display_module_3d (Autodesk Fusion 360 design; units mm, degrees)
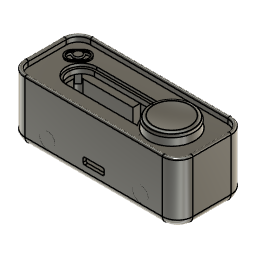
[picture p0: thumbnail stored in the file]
sketch "top&slot" plane through (0, 0, 0) normal (0, 0, 1) x axis (1, 0, 0)
  line L1 (22, -14.5) -> (22, -20.5)
  line L2 (11, 0) -> (-40.5, 0)
  line L3 (-45, 20.35) -> (45, 20.35)
  line L4 (-45, 20.5) -> (45, 20.5)
  line L5 (45, -22.5) -> (-45, -22.5)
  line L6 (-45, 15.5) -> (45, 15.5)
  line L7 (-45, 14.5) -> (45, 14.5)
  line L8 (17.5, 10) -> (17.41, 10)
  line L9 (17.5, 8.5) -> (-30.5, 8.5)
  line L10 (-14.75, 0) -> (11, 0)
  line L11 (-45, 22.5) -> (45, 22.5)
  line L12 (-20, -20.5) -> (-20, -16.5)
  line L13 (15, -14.5) -> (-15, -14.5)
  line L14 (17.5, 10) -> (-30.5, 10)
  line L15 (22, -18.4) -> (3.25, -18.4)
  line L16 (-22, -14.5) -> (-15, -14.5)
  line L17 (-55, -12.5) -> (-55, 12.5)
  line L18 (17.5, -10) -> (17.5, 10)
  line L19 (48, 12.5) -> (48, -12.5)
  line L20 (0, -20.5) -> (0, 20.5)
  line L21 (-47, -12.5) -> (-47, 12.5)
  line L22 (15, -16.5) -> (15, -14.5)
  line L23 (-15, -17.5) -> (-15, -14.5)
  line L24 (20, -16.5) -> (-20, -16.5)
  line L25 (45, -15.5) -> (-45, -15.5)
  line L26 (-8, 0) -> (-53, 0)
  line L27 (-3.25, -16.5) -> (-3.25, -18.4)
  line L28 (20, -20.5) -> (20, -16.5)
  line L29 (-15, -18.4) -> (-15, -17.5)
  line L30 (3.25, -16.5) -> (3.25, -18.4)
  line L31 (45, -20.35) -> (-45, -20.35)
  line L32 (-22, -14.5) -> (-22, -20.5)
  line L33 (-30.5, -8.5) -> (17.5, -8.5)
  line L34 (-3.25, -18.4) -> (3.25, -18.4)
  line L35 (-22, -18.4) -> (-3.25, -18.4)
  line L36 (-30.5, -10) -> (17.5, -10)
  line L37 (0, -19.5) -> (0, -14.5)
  line L38 (22, -19.5) -> (-22, -19.5)
  line L39 (22, -14.5) -> (15, -14.5)
  line L40 (45, -14.5) -> (-45, -14.5)
  line L41 (45, -20.5) -> (-45, -20.5)
  line L42 (20, -20.5) -> (20, -17.5)
  line L43 (53, 12.5) -> (53, -12.5)
  line L44 (-30.5, 10) -> (-30.5, -10)
  line L45 (-55, -22.5) -> (55, 22.5)
  line L46 (17.5, -8.5) -> (17.5, 8.5)
  line L47 (-52.85, -12.5) -> (-52.85, 12.5)
  line L48 (55, -22.5) -> (-55, 22.5)
  line L49 (47, 12.5) -> (47, -12.5)
  line L50 (55, 12.5) -> (55, -12.5)
  line L51 (-30.5, 8.5) -> (-30.5, -8.5)
  line L52 (52.85, 12.5) -> (52.85, -12.5)
  line L53 (-48, -12.5) -> (-48, 12.5)
  line L54 (-53, -12.5) -> (-53, 12.5)
  line L55 (-12.3, 15.5) -> (-45, 15.5)
  line L56 (-12.3, 20.5) -> (-12.3, 15.5)
  line L57 (-45, 20.5) -> (-12.3, 20.5)
  line L58 (-45, 15.5) -> (-45, 20.5)
  line L59 (8.3, 15.5) -> (45, 15.5)
  line L60 (8.3, 20.5) -> (8.3, 15.5)
  line L61 (45, 20.5) -> (8.3, 20.5)
  line L62 (45, 15.5) -> (45, 20.5)
  arc A1 centre (45, 12.5) radius 10 clockwise from (45, 22.5) to (55, 12.5)
  circle C1 centre (-30.5, 0) radius 10
  arc A2 centre (45, 12.5) radius 8 clockwise from (45, 20.5) to (53, 12.5)
  arc A3 centre (45, 12.5) radius 7.85 clockwise from (45, 20.35) to (52.85, 12.5)
  arc A4 centre (-30.5, 0) radius 8.5 clockwise from (-30.5, -8.5) to (-30.5, 8.5)
  arc A5 centre (-45, 12.5) radius 8 clockwise from (-53, 12.5) to (-45, 20.5)
  arc A6 centre (-45, -12.5) radius 10 clockwise from (-45, -22.5) to (-55, -12.5)
  arc A7 centre (45, 12.5) radius 2 clockwise from (45, 14.5) to (47, 12.5)
  arc A8 centre (45, -12.5) radius 7.85 clockwise from (52.85, -12.5) to (45, -20.35)
  arc A9 centre (45, -12.5) radius 10 clockwise from (55, -12.5) to (45, -22.5)
  arc A10 centre (45, -12.5) radius 2 clockwise from (47, -12.5) to (45, -14.5)
  arc A11 centre (45, 12.5) radius 3 clockwise from (45, 15.5) to (48, 12.5)
  arc A12 centre (-45, -12.5) radius 3 clockwise from (-45, -15.5) to (-48, -12.5)
  arc A13 centre (-45, -12.5) radius 7.85 clockwise from (-45, -20.35) to (-52.85, -12.5)
  arc A14 centre (-45, -12.5) radius 2 clockwise from (-45, -14.5) to (-47, -12.5)
  arc A15 centre (45, -12.5) radius 8 clockwise from (53, -12.5) to (45, -20.5)
  arc A16 centre (45, -12.5) radius 3 clockwise from (48, -12.5) to (45, -15.5)
  arc A17 centre (-45, -12.5) radius 8 clockwise from (-45, -20.5) to (-53, -12.5)
  circle C2 centre (28.635, 0.0503) radius 14.9999
  arc A18 centre (-45, 12.5) radius 7.85 clockwise from (-52.85, 12.5) to (-45, 20.35)
  circle C3 centre (28.635, 0.0503) radius 15.9999
  arc A19 centre (-45, 12.5) radius 3 clockwise from (-48, 12.5) to (-45, 15.5)
  arc A20 centre (-45, 12.5) radius 10 clockwise from (-55, 12.5) to (-45, 22.5)
  arc A21 centre (-45, 12.5) radius 2 clockwise from (-47, 12.5) to (-45, 14.5)
  point P89 (0, 0)
  point P94 (0, 0)
  point P92 (-55, 22.5)
  point P93 (-55, -22.5)
  point P90 (55, -22.5)
  point P91 (55, 22.5)
  point P100 (-53, 0)
  point P98 (-8, 0)
  point P99 (-8, 0)
  point P96 (-40.5, 0)
  point P102 (-14.75, 0)
  point P97 (-14.75, 0)
  point P37 (0, 20.5)
  point P86 (0, -14.5)
  point P87 (0, -19.5)
  point P88 (0, -20.5)
  point P51 (-30.5, 10)
  point P66 (17.41, 10)
  point P54 (17.5, -10)
  point P64 (17.5, -8.5)
  point P72 (-30.5, 8.5)
  point P47 (22, -19.5)
  point P5 (22, -20.5)
  point P25 (-22, -19.5)
  point P2 (-22, -20.5)
  point P3 (-20, -20.5)
  point P53 (17.5, 10)
  point P52 (-30.5, -10)
  point P71 (-30.5, -8.5)
  point P105 (-45, 15.5)
  point P119 (-12.3, 15.5)
  point P114 (45, 15.5)
  point P122 (8.3, 15.5)
  point P124 (45, 20.5)
  horizontal L11
  perpendicular L11 L17
  parallel L5 L11
  parallel L17 L50
  coincident P89 L45
  coincident P89 L48
  coincident P89 P94
  coincident P92 L11
  coincident P92 L17
  tangent L11 A20
  tangent L17 A20
  coincident P93 L17
  coincident P93 L5
  tangent L17 A6
  tangent L5 A6
  equal A6 A20
  coincident P90 L50
  coincident P90 L5
  tangent A9 L50
  tangent L5 A9
  equal A9 A20
  coincident P91 L11
  coincident P91 L50
  tangent A1 L11
  tangent A1 L50
  equal A1 A20
  midpoint P100 L54
  perpendicular L26 L54
  coincident P98 P99
  coincident P96 C1
  coincident P96 L26
  midpoint P102 L2
  coincident P97 P102
  midpoint P37 L4
  perpendicular L20 L41
  midpoint P86 L13
  midpoint P87 L38
  coincident P88 L41
  horizontal L14
  vertical L18
  horizontal L36
  vertical L44
  coincident P51 C1
  coincident P66 L14
  coincident P66 C2
  coincident P54 C2
  horizontal L9
  vertical L46
  horizontal L33
  vertical L51
  coincident P64 L18
  coincident P72 L44
  concentric C1 A4
  coincident P47 L1
  coincident P5 L41
  coincident P25 L32
  coincident P2 L41
  coincident P3 L41
  horizontal L55
  vertical L56
  horizontal L57
  vertical L58
  horizontal L59
  vertical L60
  horizontal L61
  vertical L62
  dimension "d1" = -2
  dimension "d2" = -2.15
  dimension "d3" = 1
  dimension "d4" = -8
  dimension "d5" = -7
  dimension "d6" distance P90 P93 = 110
  dimension "d7" distance P92 P93 = 45
  dimension "d8" radius A20 = 10
  dimension "d9" distance P99 P100 = 45
  dimension "d10" distance P51 P53 = 48
  dimension "d11" distance P51 P52 = 20
  dimension "d12" distance P71 P72 = 17
  dimension "d56" distance P105 P119 = 32.7
  dimension "d57" distance P114 P122 = 36.7
  dimension "d58" distance P114 P124 = 5
extrude "Extrude1" new body sketch "top&slot" profile of L1 L9 C1 L12 L13 L14 L15 L16 L22 L23 L24 L27 L28 L29 L30 L32 L33 L34 L35 L36 L38 L39 L42 C2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 along normal blind 5
sketch "switch" plane through (0, 0, 0) normal (0, 0, 1) x axis (1, 0, 0)
  line L1 (-72.5, -10.85) -> (-72.5, -1.85)
  line L2 (-71.5, -6.35) -> (-89.5, -6.35)
  line L3 (-74.5, -2.85) -> (-86.5, -9.85)
  line L4 (-88.5, -10.85) -> (-72.5, -10.85)
  line L5 (-74.5, -2.85) -> (-86.5, -2.85)
  line L6 (-86.5, -2.85) -> (-86.5, -9.85)
  line L7 (-88.5, -1.85) -> (-72.5, -10.85)
  line L8 (-71.5, -1.6) -> (-89.5, -1.6)
  line L9 (-88.5, -1.85) -> (-88.5, -10.85)
  line L10 (-80.5, -11.1) -> (-80.5, -1.6)
  line L11 (-89.5, -1.6) -> (-89.5, -11.1)
  line L12 (-86.5, -2.85) -> (-74.5, -9.85)
  line L13 (-72.5, -1.85) -> (-88.5, -1.85)
  line L14 (-74.5, -9.85) -> (-74.5, -2.85)
  line L15 (-89.5, -11.1) -> (-71.5, -11.1)
  line L16 (-71.5, -11.1) -> (-71.5, -1.6)
  line L17 (-72.5, -1.85) -> (-88.5, -10.85)
  line L18 (-86.5, -9.85) -> (-74.5, -9.85)
  line L19 (-32.6602, 12.746) -> (-39.3777, 19.4635)
  line L20 (-45.3881, 0.0181) -> (-32.6602, 12.746)
  line L21 (-39.3777, 19.4635) -> (-52.1057, 6.7356)
  line L22 (-52.1057, 6.7356) -> (-45.3881, 0.0181)
  line L23 (-33.5441, 12.2157) -> (-39.9081, 18.5796)
  line L24 (-44.8578, 0.902) -> (-33.5441, 12.2157)
  line L25 (-39.9081, 18.5796) -> (-51.2218, 7.2659)
  line L26 (-51.2218, 7.2659) -> (-44.8578, 0.902)
  line L27 (-34.2512, 11.5086) -> (-40.6152, 17.8725)
  line L28 (-44.1507, 1.6091) -> (-34.2512, 11.5086)
  line L29 (-40.6152, 17.8725) -> (-50.5147, 7.973)
  line L30 (-50.5147, 7.973) -> (-44.1507, 1.6091)
  line L31 (-35.6654, 11.5086) -> (-40.6152, 16.4583)
  line L32 (-44.1507, 3.0233) -> (-35.6654, 11.5086)
  line L33 (-40.6152, 16.4583) -> (-49.1005, 7.973)
  line L34 (-49.1005, 7.973) -> (-44.1507, 3.0233)
  line L35 (16.1856, -10) -> (-30.5, -10)
  line L36 (-30.5, 10) -> (16.105, 10)
  line L37 (22, -14.5) -> (22, -14.509)
  line L38 (21.9803, -14.5) -> (22, -14.5)
  line L39 (52.85, -12.5) -> (52.85, 12.5)
  line L40 (-45, -20.35) -> (45, -20.35)
  line L41 (-52.85, 12.5) -> (-52.85, -12.5)
  line L42 (45, 20.35) -> (-45, 20.35)
  line L43 (-52.35, 12.5) -> (-52.35, -12.5)
  line L44 (-45, -19.85) -> (45, -19.85)
  line L45 (52.35, -12.5) -> (52.35, 12.5)
  line L46 (45, 19.85) -> (-45, 19.85)
  circle C1 centre (-80.5, -6.35) radius 3.25
  circle C2 centre (-42.3829, 9.7408) radius 3.25
  arc A1 centre (-30.5, 0) radius 10 clockwise from (-30.5, -10) to (-30.5, 10)
  arc A2 centre (28.635, 0.0503) radius 15.9999 clockwise from (16.1856, -10) to (16.105, 10)
  circle C3 centre (28.635, 0.0503) radius 14.9999
  arc A3 centre (28.635, 0.0503) radius 15.9999 clockwise from (22, -14.509) to (21.9803, -14.5)
  arc A4 centre (45, -12.5) radius 7.85 clockwise from (52.85, -12.5) to (45, -20.35)
  arc A5 centre (-45, -12.5) radius 7.85 clockwise from (-45, -20.35) to (-52.85, -12.5)
  arc A6 centre (-45, 12.5) radius 7.85 clockwise from (-52.85, 12.5) to (-45, 20.35)
  arc A7 centre (45, 12.5) radius 7.85 clockwise from (45, 20.35) to (52.85, 12.5)
  arc A8 centre (-45, 12.5) radius 7.35 clockwise from (-52.35, 12.5) to (-45, 19.85)
  arc A9 centre (-45, -12.5) radius 7.35 clockwise from (-45, -19.85) to (-52.35, -12.5)
  arc A10 centre (45, -12.5) radius 7.35 clockwise from (52.35, -12.5) to (45, -19.85)
  arc A11 centre (45, 12.5) radius 7.35 clockwise from (45, 19.85) to (52.35, 12.5)
  point P13 (-80.5, -1.6)
  point P4 (-80.5, -11.1)
  point P5 (-89.5, -6.35)
  point P6 (-71.5, -6.35)
  point P9 (-80.5, -6.35)
  point P15 (-80.5, -6.35)
  point P23 (-80.5, -6.35)
  point P2 (-89.5, -1.6)
  point P8 (-71.5, -1.6)
  point P3 (-89.5, -11.1)
  point P12 (-86.5, -2.85)
  point P14 (-74.5, -2.85)
  point P11 (-86.5, -9.85)
  point P17 (-88.5, -1.85)
  point P19 (-72.5, -1.85)
  point P18 (-88.5, -10.85)
  point P32 (-52.1057, 6.7356)
  point P37 (-39.3777, 19.4635)
  point P20 (-45.3881, 0.0181)
  point P27 (-40.6152, 16.4583)
  point P30 (-49.1005, 7.973)
  point P24 (-44.1507, 3.0233)
  point P26 (-51.2218, 7.2659)
  point P28 (-39.9081, 18.5796)
  point P31 (-44.8578, 0.902)
  midpoint P13 L8
  midpoint P4 L15
  midpoint P5 L11
  midpoint P6 L16
  midpoint P9 L10
  perpendicular L6 L18
  parallel L5 L18
  parallel L6 L14
  coincident P15 L12
  coincident P15 L3
  coincident P9 P15
  perpendicular L4 L9
  parallel L4 L13
  parallel L1 L9
  coincident P23 L7
  coincident P23 L17
  coincident P9 P23
  perpendicular L32 L34
  parallel L32 L33
  parallel L31 L34
  perpendicular L24 L26
  parallel L24 L25
  parallel L23 L26
  dimension "d15" = -1
  dimension "d16" distance P2 P8 = 18
  dimension "d17" distance P2 P3 = 9.5
  dimension "d18" diameter C1 = 6.5
  dimension "d19" distance P12 P14 = 12
  dimension "d20" distance P11 P12 = 7
  dimension "d21" distance P17 P19 = 16
  dimension "d22" distance P17 P18 = 9
  dimension "d23" distance P32 P37 = 18
  dimension "d24" distance P20 P32 = 9.5
  dimension "d25" diameter C2 = 6.5
  dimension "d26" distance P27 P30 = 12
  dimension "d27" distance P24 P30 = 7
  dimension "d28" distance P26 P28 = 16
  dimension "d29" distance P26 P31 = 9
  dimension "d82" = 0.5
extrude "Extrude2" new body sketch "top&slot" profile of L1 A1 L5 L8 L9 C1 L11 L12 L13 L14 L15 L16 L17 L18 A4 L22 A6 L23 L24 L27 L28 A9 L29 L30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 along normal blind 9.9 (= "7 mm + 2.9 mm") and against normal blind 30
extrude "Extrude3" add sketch "top&slot" profile of L9 C1 L14 A4 L33 L36 L44 C3 along normal blind 3.1
shell "Shell1" innerThickness 2
fillet "Fillet1" radius 5
extrude "Extrude4" sketch "top&slot" profile of L1 L12 L15 L22 L23 L24 L28 L32 L34 L35 L38 L42 L4 L54 L41 L43 A5 A17 A15 A2 L3 L47 L31 L52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 blind 17.2 (= "19.2 mm - 2 mm")
sketch "magnet" plane through (0, -15.5, 0) normal (0, 1, 0) x axis (-1, 0, 0)
  line L1 (-15, -28) -> (-45, -28)
  line L2 (-15, -10.8) -> (-15, -28)
  line L3 (-45, -10.8) -> (-15, -10.8)
  line L4 (-45, -28) -> (-45, -10.8)
  line L5 (45, -28) -> (15, -28)
  line L6 (45, -10.8) -> (45, -28)
  line L7 (15, -10.8) -> (45, -10.8)
  line L8 (15, -28) -> (15, -10.8)
  line L9 (-30.5, -19.4) -> (-15, -19.4)
  line L10 (-15, -19.4) -> (15, -19.4)
  line L11 (0, -32) -> (0, -19.4)
  circle C1 centre (-30.5, -19.4) radius 5.1
  circle C2 centre (30.5, -19.4) radius 5.1
  point P10 (-15, -19.4)
  point P11 (-30.5, -19.4)
  point P12 (-30.5, -19.4)
  point P13 (15, -19.4)
  point P14 (0, -19.4)
  midpoint L2 P10
  perpendicular L2 L9
  coincident P11 P12
  midpoint L8 P13
  midpoint L10 P14
  perpendicular L10 L11
  symmetric C1 L11 C2
  dimension "d42" distance P10 P11 = 15.5
  dimension "d43" diameter C1 = 10.2
extrude "Extrude5" cut sketch "magnet" profile of C1 C2 against normal blind 6.5
sketch "usb" plane through (0, 22.5, 0) normal (0, 1, 0) x axis (-1, 0, 0)
  line L1 (45, -25) -> (-45, -25)
  line L2 (45, 9.9) -> (45, -25)
  line L3 (-45, 9.9) -> (45, 9.9)
  line L4 (-45, -25) -> (-45, 9.9)
  line L5 (-3.5, -20.78) -> (5.5, -20.78)
  line L6 (-3.5, -17.58) -> (-3.5, -20.78)
  line L7 (5.5, -17.58) -> (-3.5, -17.58)
  line L8 (5.5, -20.78) -> (5.5, -17.58)
  line L9 (5.7, -17.38) -> (-3.7, -17.38)
  line L10 (5.7, -20.98) -> (5.7, -17.38)
  line L11 (-3.7, -20.98) -> (5.7, -20.98)
  line L12 (-3.7, -17.38) -> (-3.7, -20.98)
  point P6 (5.5, -20.78)
  point P7 (-3.5, -20.78)
  point P9 (5.5, -17.58)
  horizontal L5
  vertical L6
  horizontal L7
  vertical L8
  dimension "d49" distance P6 P7 = 9
  dimension "d50" distance P6 P9 = 3.2
  dimension "d51" = -0.2
extrude "Extrude6" cut sketch "usb" profile of L5 L6 L7 L8 L10 L11 L9 L12 against normal blind 8
fillet "Fillet2" radius 1.5
extrude "Extrude7" cut sketch "top&slot" profile of L4 L3 L6 L56 L60 to an object
sketch "pogo" plane through (0, -18.4, 0) normal (0, 1, 0) x axis (-1, 0, 0)
  line L1 (20, -28) -> (-20, -28)
  line L2 (20, -10.8) -> (20, -28)
  line L3 (-20, -10.8) -> (20, -10.8)
  line L4 (-20, -28) -> (-20, -10.8)
  line L5 (10, -24) -> (-10, -24)
  line L6 (20, -28) -> (-20, -28)
  line L7 (-20, -16.4) -> (-1.7101, -16.4)
  line L8 (-6.92, -17.81) -> (-6.92, -20.19)
  line L9 (5.92, -16.81) -> (-5.92, -16.81)
  line L10 (-1.7101, -16.4) -> (0, -16.4)
  line L11 (20, -16.4) -> (0, -16.4)
  line L12 (20, -4.8) -> (20, -28)
  line L13 (20, -28) -> (-20, -28)
  line L14 (20, -11.8) -> (20, -28)
  line L15 (-20, -11.8) -> (20, -11.8)
  line L16 (6.92, -20.19) -> (6.92, -17.81)
  line L17 (-20, -4.8) -> (20, -4.8)
  line L18 (0, -28) -> (0, -4.8)
  line L19 (0, -24) -> (0, -14)
  line L20 (-20, -28) -> (-20, -4.8)
  line L21 (-10, -14) -> (10, -14)
  line L22 (-5.92, -21.19) -> (5.92, -21.19)
  line L23 (-20, -28) -> (-20, -11.8)
  line L24 (24, -28) -> (0, -28)
  arc A1 centre (-10, -19) radius 5 clockwise from (-10, -24) to (-15, -19)
  arc A2 centre (-5.92, -17.81) radius 1 clockwise from (-6.92, -17.81) to (-5.92, -16.81)
  arc A3 centre (10, -19) radius 5 clockwise from (15, -19) to (10, -24)
  arc A4 centre (5.92, -20.19) radius 1 clockwise from (6.92, -20.19) to (5.92, -21.19)
  arc A5 centre (5.92, -17.81) radius 1 clockwise from (5.92, -16.81) to (6.92, -17.81)
  arc A6 centre (10, -19) radius 5 clockwise from (10, -14) to (15, -19)
  arc A7 centre (-5.92, -20.19) radius 1 clockwise from (-5.92, -21.19) to (-6.92, -20.19)
  arc A8 centre (-10, -19) radius 5 clockwise from (-15, -19) to (-10, -14)
  point P13 (0, -4.8)
  point P29 (0, -28)
  point P44 (0, -16.4)
  point P12 (-20, -16.4)
  point P37 (20, -16.4)
  point P42 (15, -19)
  point P43 (15, -19)
  point P6 (-15, -19)
  point P40 (-15, -19)
  point P22 (0, -14)
  point P24 (0, -24)
  midpoint P13 L17
  midpoint P29 L6
  midpoint P44 L18
  perpendicular L10 L18
  midpoint P12 L20
  perpendicular L7 L20
  midpoint P37 L12
  perpendicular L18 L24
  horizontal L5
  horizontal L21
  tangent A6 L21
  tangent L5 A3
  equal A3 A6
  coincident P42 P43
  tangent L21 A8
  equal A6 A8
  tangent L5 A1
  equal A1 A6
  coincident P6 P40
  horizontal L22
  perpendicular L8 L22
  parallel L9 L22
  parallel L8 L16
  tangent A2 L8
  tangent A2 L9
  tangent L8 A7
  tangent A7 L22
  equal A2 A7
  tangent A4 L22
  tangent A4 L16
  equal A2 A4
  tangent L9 A5
  tangent A5 L16
  midpoint P22 L21
  midpoint P24 L5
  dimension "d61" radius A6 = 5
  dimension "d62" distance L5 L21 = 10
  dimension "d63" radius A2 = 1
  dimension "d64" radius A5 = 1
extrude "Extrude8" cut sketch "pogo" profile of L5 A1 A2 L8 A3 L9 A4 A5 A6 L16 A7 L19 L21 L22 A8 against normal blind 2.1
sketch "slider" plane through (0, 0, 0) normal (0, 0, -1) x axis (1, 0, 0)
  line L1 (-30.5, -8.5) -> (15.0483, -8.5)
  line L2 (15.1114, 8.5) -> (-30.5, 8.5)
  line L3 (22, 14.5) -> (22, 14.509)
  line L4 (21.9803, 14.5) -> (22, 14.5)
  line L5 (52.85, 12.5) -> (52.85, -12.5)
  line L6 (-45, 20.35) -> (45, 20.35)
  line L7 (-52.85, -12.5) -> (-52.85, 12.5)
  line L8 (45, -20.35) -> (-45, -20.35)
  line L9 (-50.5725, -7.9652) -> (-40.673, -17.8647)
  line L10 (-40.673, -17.8647) -> (-34.3091, -11.5007)
  line L11 (-42.4408, -20.35) -> (-42.4408, -9.7329)
  line L12 (-33.602, -12.2078) -> (-44.9157, -0.8941)
  line L13 (-45, -9.7329) -> (-45, -20.35)
  line L14 (-34.3091, -11.5007) -> (-44.2086, -1.6012)
  line L15 (-51.2796, -7.2581) -> (-39.9659, -18.5718)
  line L16 (-44.2086, -3.0154) -> (-49.1583, -7.9652)
  line L17 (-44.2086, -1.6012) -> (-50.5725, -7.9652)
  line L18 (-45.446, -0.0102) -> (-52.1635, -6.7277)
  line L19 (-52.4408, -12.5) -> (-52.85, -12.5)
  line L20 (-35.7233, -11.5007) -> (-44.2086, -3.0154)
  line L21 (-49.1583, -7.9652) -> (-40.673, -16.4505)
  line L22 (-39.4356, -19.4557) -> (-32.7181, -12.7382)
  line L23 (-39.9659, -18.5718) -> (-33.602, -12.2078)
  line L24 (-52.1635, -6.7277) -> (-39.4356, -19.4557)
  line L25 (-42.4408, -12.5) -> (-52.4408, -12.5)
  line L26 (-52.85, -9.7329) -> (-42.4408, -9.7329)
  line L27 (-32.7181, -12.7382) -> (-45.446, -0.0102)
  line L28 (-44.9157, -0.8941) -> (-51.2796, -7.2581)
  line L29 (-40.673, -16.4505) -> (-35.7233, -11.5007)
  arc A1 centre (28.635, -0.0503) radius 15.9999 clockwise from (15.0483, -8.5) to (15.1114, 8.5)
  arc A2 centre (-30.5, 0) radius 8.5 clockwise from (-30.5, -8.5) to (-30.5, 8.5)
  circle C1 centre (28.635, -0.0503) radius 14.9999
  arc A3 centre (28.635, -0.0503) radius 15.9999 clockwise from (21.9803, 14.5) to (22, 14.509)
  arc A4 centre (45, 12.5) radius 7.85 clockwise from (45, 20.35) to (52.85, 12.5)
  arc A5 centre (-45, 12.5) radius 7.85 clockwise from (-52.85, 12.5) to (-45, 20.35)
  arc A6 centre (-45, -12.5) radius 7.85 clockwise from (-45, -20.35) to (-52.85, -12.5)
  arc A7 centre (45, -12.5) radius 7.85 clockwise from (52.85, -12.5) to (45, -20.35)
  circle C2 centre (-42.4408, -9.7329) radius 3.25
  point P36 (-42.4408, -9.7329)
  point P48 (-42.4408, -9.7329)
  point P24 (-52.85, -12.5)
  point P49 (-52.85, -12.5)
  point P51 (-42.4408, -12.5)
  point P23 (-45, -20.35)
  point P45 (-45, -20.35)
  point P46 (-45, -9.7329)
  point P39 (-39.4356, -19.4557)
  point P44 (-52.1635, -6.7277)
  point P28 (-32.7181, -12.7382)
  point P34 (-49.1583, -7.9652)
  point P37 (-40.673, -16.4505)
  point P31 (-35.7233, -11.5007)
  point P33 (-39.9659, -18.5718)
  point P35 (-51.2796, -7.2581)
  point P38 (-33.602, -12.2078)
  perpendicular L20 L29
  parallel L20 L21
  parallel L16 L29
  perpendicular L12 L23
  parallel L12 L15
  parallel L23 L28
  coincident P36 P48
  coincident P24 P49
  coincident P51 L11
  perpendicular L11 L25
  coincident P23 P45
  coincident P46 L26
  perpendicular L13 L26
  dimension "d84" distance P39 P44 = 18
  dimension "d85" distance P28 P39 = 9.5
  dimension "d86" diameter C2 = 6.5
  dimension "d87" distance P34 P37 = 12
  dimension "d88" distance P31 P37 = 7
  dimension "d89" distance P33 P35 = 16
  dimension "d90" distance P33 P38 = 9
extrude "Extrude15" cut sketch "slider" profile of L16 L20 L21 C2 L29 along normal blind 9
extrude "Extrude17" sketch "slider" profile of L12 L15 L16 L18 L20 L21 L22 L23 L24 L27 L28 L29 L17 L14 L9 L10 blind -3.5
extrude "Extrude18" sketch "slider" profile of L12 L15 L16 L20 L21 L23 L28 C2 L29 L17 L14 L9 L10 blind 1 bodies "switch"
fillet "Fillet3" radius 4.4
fillet "Fillet4" radius 4.5
sketch "sliderclose" plane through (0, 0, 0) normal (0, 0, -1) x axis (1, 0, 0)
  line L1 (-48.628, -3.1922) -> (-48.9815, -3.5458)
  line L2 (-35.9001, -9.5562) -> (-42.264, -3.1922)
  line L3 (-36.2536, -16.2737) -> (-35.9001, -15.9201)
  line L4 (-48.9815, -9.9097) -> (-42.6176, -16.2737)
  line L5 (-30.5, -8.5) -> (15.0483, -8.5)
  line L6 (15.1114, 8.5) -> (-30.5, 8.5)
  line L7 (22, 14.5) -> (22, 14.509)
  line L8 (21.9803, 14.5) -> (22, 14.5)
  line L9 (52.85, 12.5) -> (52.85, -12.5)
  line L10 (-45, 20.35) -> (45, 20.35)
  line L11 (-52.85, -12.5) -> (-52.85, 12.5)
  line L12 (45, -20.35) -> (-45, -20.35)
  line L13 (-42.6176, -16.2737) -> (-48.9815, -9.9097)
  line L14 (-35.9001, -15.9201) -> (-36.2536, -16.2737)
  line L15 (-42.264, -3.1922) -> (-35.9001, -9.5562)
  line L16 (-48.9815, -3.5458) -> (-48.628, -3.1922)
  line L17 (-43.3247, -16.9808) -> (-49.6887, -10.6168)
  line L18 (-35.193, -16.6272) -> (-35.5465, -16.9808)
  line L19 (-41.5569, -2.4851) -> (-35.193, -8.8491)
  line L20 (-49.6887, -2.8387) -> (-49.3351, -2.4851)
  line L21 (-49.6179, -2.9094) -> (-49.2644, -2.5558)
  line L22 (-43.254, -16.9101) -> (-49.6179, -10.5461)
  line L23 (-35.2637, -16.5565) -> (-35.6172, -16.9101)
  line L24 (-41.6276, -2.5558) -> (-35.2637, -8.9198)
  arc A1 centre (-45.446, -6.3742) radius 4.5 clockwise from (-48.628, -3.1922) to (-42.264, -3.1922)
  arc A2 centre (-39.0821, -12.7382) radius 4.5 clockwise from (-35.9001, -9.5562) to (-35.9001, -15.9201)
  arc A3 centre (-39.4356, -13.0917) radius 4.5 clockwise from (-36.2536, -16.2737) to (-42.6176, -16.2737)
  arc A4 centre (-45.7996, -6.7277) radius 4.5 clockwise from (-48.9815, -9.9097) to (-48.9815, -3.5458)
  arc A5 centre (28.635, -0.0503) radius 15.9999 clockwise from (15.0483, -8.5) to (15.1114, 8.5)
  arc A6 centre (-30.5, 0) radius 8.5 clockwise from (-30.5, -8.5) to (-30.5, 8.5)
  circle C1 centre (28.635, -0.0503) radius 14.9999
  arc A7 centre (28.635, -0.0503) radius 15.9999 clockwise from (21.9803, 14.5) to (22, 14.509)
  arc A8 centre (45, 12.5) radius 7.85 clockwise from (45, 20.35) to (52.85, 12.5)
  arc A9 centre (-45, 12.5) radius 7.85 clockwise from (-52.85, 12.5) to (-45, 20.35)
  arc A10 centre (-45, -12.5) radius 7.85 clockwise from (-45, -20.35) to (-52.85, -12.5)
  arc A11 centre (45, -12.5) radius 7.85 clockwise from (52.85, -12.5) to (45, -20.35)
  arc A12 centre (-45.7996, -6.7277) radius 4.5 clockwise from (-48.9815, -9.9097) to (-48.9815, -3.5458)
  arc A13 centre (-39.4356, -13.0917) radius 4.5 clockwise from (-36.2536, -16.2737) to (-42.6176, -16.2737)
  arc A14 centre (-39.0821, -12.7382) radius 4.5 clockwise from (-35.9001, -9.5562) to (-35.9001, -15.9201)
  arc A15 centre (-45.446, -6.3742) radius 4.5 clockwise from (-48.628, -3.1922) to (-42.264, -3.1922)
  arc A16 centre (-45.7996, -6.7277) radius 5.5 clockwise from (-49.6887, -10.6168) to (-49.6887, -2.8387)
  arc A17 centre (-39.4356, -13.0917) radius 5.5 clockwise from (-35.5465, -16.9808) to (-43.3247, -16.9808)
  arc A18 centre (-39.0821, -12.7382) radius 5.5 clockwise from (-35.193, -8.8491) to (-35.193, -16.6272)
  arc A19 centre (-45.446, -6.3742) radius 5.5 clockwise from (-49.3351, -2.4851) to (-41.5569, -2.4851)
  arc A20 centre (-45.7996, -6.7277) radius 5.4 clockwise from (-49.6179, -10.5461) to (-49.6179, -2.9094)
  arc A21 centre (-39.4356, -13.0917) radius 5.4 clockwise from (-35.6172, -16.9101) to (-43.254, -16.9101)
  arc A22 centre (-39.0821, -12.7382) radius 5.4 clockwise from (-35.2637, -8.9198) to (-35.2637, -16.5565)
  arc A23 centre (-45.446, -6.3742) radius 5.4 clockwise from (-49.2644, -2.5558) to (-41.6276, -2.5558)
  dimension "d105" = 1
  dimension "d108" = 0.9
extrude "Extrude19" cut sketch "sliderclose" profile of L1 A1 L2 A2 L3 A3 L4 A4 A12 L13 A13 L14 A14 L15 A15 L16 L19 L17 A17 L20 A18 A16 A19 L18 against normal blind 2.2
extrude "Extrude20" sketch "slider" profile of C2 blind -4
fillet "Fillet5" radius 3.4
extrude "Extrude21" add sketch "slider" profile of L12 L15 L16 L20 L21 L29 L17 L14 L9 L10 against normal blind 1
fillet "Fillet6" radius 3.4
fillet "Fillet7" radius 3.4
fillet "Fillet8" radius 4.4
sketch "bottommount" plane through (0, 0, -28) normal (0, 0, 1) x axis (-1, 0, 0)
  line L1 (-45, 15.5) -> (-15, 15.5)
  line L2 (-48, -12.5) -> (-48, 12.5)
  line L3 (-8.3, -15.5) -> (-45, -15.5)
  line L4 (-8.3, -20.5) -> (-8.3, -15.5)
  line L5 (12.3, -20.5) -> (-8.3, -20.5)
  line L6 (12.3, -15.5) -> (12.3, -20.5)
  line L7 (45, -15.5) -> (12.3, -15.5)
  line L8 (48, 12.5) -> (48, -12.5)
  line L9 (15, 15.5) -> (45, 15.5)
  line L10 (15, 16.5) -> (15, 15.5)
  line L11 (20, 16.5) -> (15, 16.5)
  line L12 (20, 18.4) -> (20, 16.5)
  line L13 (-20, 18.4) -> (20, 18.4)
  line L14 (-20, 16.5) -> (-20, 18.4)
  line L15 (-15, 16.5) -> (-20, 16.5)
  line L16 (-15, 15.5) -> (-15, 16.5)
  line L17 (-45, 22.5) -> (45, 22.5)
  line L18 (55, 12.5) -> (55, -12.5)
  line L19 (45, -22.5) -> (-45, -22.5)
  line L20 (-55, -12.5) -> (-55, 12.5)
  line L21 (-55, -12.5) -> (-55, 12.5)
  line L22 (45, -22.5) -> (-45, -22.5)
  line L23 (-45, 22.5) -> (45, 22.5)
  line L24 (55, 12.5) -> (55, -12.5)
  arc A1 centre (-45, 12.5) radius 3 clockwise from (-48, 12.5) to (-45, 15.5)
  arc A2 centre (-45, -12.5) radius 3 clockwise from (-45, -15.5) to (-48, -12.5)
  arc A3 centre (45, -12.5) radius 3 clockwise from (48, -12.5) to (45, -15.5)
  arc A4 centre (45, 12.5) radius 3 clockwise from (45, 15.5) to (48, 12.5)
  arc A5 centre (45, 12.5) radius 10 clockwise from (45, 22.5) to (55, 12.5)
  arc A6 centre (-45, -12.5) radius 10 clockwise from (-45, -22.5) to (-55, -12.5)
  arc A7 centre (-45, -12.5) radius 10 clockwise from (-45, -22.5) to (-55, -12.5)
  arc A8 centre (45, 12.5) radius 10 clockwise from (45, 22.5) to (55, 12.5)
  circle C1 centre (43.3243, 10.3844) radius 4
  circle C2 centre (43.3243, 10.3844) radius 2.825
  circle C3 centre (-43.8087, -11.3516) radius 2.825
  circle C4 centre (-43.8087, -11.3516) radius 4
  circle C5 centre (43.3243, 10.3844) radius 1.4
  circle C6 centre (-43.8087, -11.3516) radius 1.55
  dimension "d128" diameter C1 = 8
  dimension "d129" diameter C2 = 5.65
  dimension "d130" diameter C5 = 2.8
  dimension "d131" diameter C6 = 3.1
  dimension "d132" diameter C3 = 5.65
  dimension "d133" diameter C4 = 8
extrude "Extrude22" cut sketch "bottommount" profile of A4 L9 C1 C2 C3 C4 C5 C6 against normal blind 20
extrude "Extrude23" new body sketch "bottommount" profile of A4 L9 C1 C2 C3 C4 along normal blind 9
extrude "Extrude24" cut of existing geometry blind -15
extrude "Extrude25" add sketch "bottommount" profile of C2 C3 C5 C6 blind 5 from offset 2
sketch "Sketch11" plane through (0, 0, 0) normal (0, 0, -1) x axis (1, 0, 0)
  line L1 (-49.3351, -2.4851) -> (-49.6887, -2.8387)
  line L2 (-35.193, -8.8491) -> (-41.5569, -2.4851)
  line L3 (-35.5465, -16.9808) -> (-35.193, -16.6272)
  line L4 (-49.6887, -10.6168) -> (-43.3247, -16.9808)
  line L5 (-30.5, -8.5) -> (15.0483, -8.5)
  line L6 (15.1114, 8.5) -> (-30.5, 8.5)
  line L7 (22, 14.5) -> (22, 14.509)
  line L8 (21.9803, 14.5) -> (22, 14.5)
  line L9 (52.85, 12.5) -> (52.85, -12.5)
  line L10 (-45, 20.35) -> (45, 20.35)
  line L11 (-52.85, -12.5) -> (-52.85, 12.5)
  line L12 (45, -20.35) -> (-45, -20.35)
  arc A1 centre (-45.7996, -6.7277) radius 5.5 clockwise from (-49.6887, -10.6168) to (-49.6887, -2.8387)
  arc A2 centre (-45.446, -6.3742) radius 5.5 clockwise from (-49.3351, -2.4851) to (-41.5569, -2.4851)
  arc A3 centre (-39.0821, -12.7382) radius 5.5 clockwise from (-35.193, -8.8491) to (-35.193, -16.6272)
  arc A4 centre (-39.4356, -13.0917) radius 5.5 clockwise from (-35.5465, -16.9808) to (-43.3247, -16.9808)
  arc A5 centre (28.635, -0.0503) radius 15.9999 clockwise from (15.0483, -8.5) to (15.1114, 8.5)
  arc A6 centre (-30.5, 0) radius 8.5 clockwise from (-30.5, -8.5) to (-30.5, 8.5)
  circle C1 centre (28.635, -0.0503) radius 14.9999
  arc A7 centre (28.635, -0.0503) radius 15.9999 clockwise from (21.9803, 14.5) to (22, 14.509)
  arc A8 centre (45, 12.5) radius 7.85 clockwise from (45, 20.35) to (52.85, 12.5)
  arc A9 centre (-45, 12.5) radius 7.85 clockwise from (-52.85, 12.5) to (-45, 20.35)
  arc A10 centre (-45, -12.5) radius 7.85 clockwise from (-45, -20.35) to (-52.85, -12.5)
  arc A11 centre (45, -12.5) radius 7.85 clockwise from (52.85, -12.5) to (45, -20.35)
  circle C2 centre (-43.3243, 10.3844) radius 4
  circle C3 centre (-43.3243, 10.3844) radius 2.825
  circle C4 centre (-43.3243, 10.3844) radius 1.4
  circle C5 centre (43.8087, -11.3516) radius 4
  circle C6 centre (43.8087, -11.3516) radius 2.825
  circle C7 centre (43.8087, -11.3516) radius 1.55
  circle C8 centre (-43.3243, 10.3844) radius 2.725
  circle C9 centre (43.8087, -11.3516) radius 2.725
  dimension "d143" = -0.1
  dimension "d144" = -0.1
extrude "Extrude26" add sketch "Sketch11" profile of C4 C7 C8 C9 to an object
fillet "Fillet9" radius 0.5
fillet "Fillet10" radius 0.5
sketch "Sketch12" plane through (0, 0, 2.5) normal (0, 0, -1) x axis (1, 0, 0)
  line L1 (-41.8044, -4.0054) -> (-36.7132, -9.0966)
  line L2 (-48.1684, -4.1468) -> (-48.027, -4.0054)
  line L3 (-43.0772, -15.4605) -> (-48.1684, -10.3693)
  line L4 (-36.7132, -15.3191) -> (-36.8547, -15.4605)
  line L5 (-48.0977, -4.0761) -> (-36.784, -15.3898)
  line L6 (-39.2588, -6.551) -> (-45.6228, -12.9149)
  line L7 (-47.5673, -3.5458) -> (-36.2536, -14.8595)
  line L8 (-48.628, -4.6064) -> (-37.3143, -15.9201)
  line L9 (-38.7285, -7.0813) -> (-45.0925, -13.4453)
  line L10 (-39.7892, -6.0206) -> (-46.1531, -12.3846)
  line L11 (-43.5015, -9.7329) -> (-42.4408, -10.7936)
  line L12 (-40.673, -6.9045) -> (-43.5015, -9.7329)
  line L13 (-39.6124, -7.9652) -> (-40.673, -6.9045)
  line L14 (-42.4408, -10.7936) -> (-39.6124, -7.9652)
  line L15 (-40.673, -5.4903) -> (-44.9157, -9.7329)
  line L16 (-38.1982, -7.9652) -> (-40.673, -5.4903)
  line L17 (-42.4408, -12.2078) -> (-38.1982, -7.9652)
  line L18 (-44.9157, -9.7329) -> (-42.4408, -12.2078)
  line L19 (-46.8602, -2.8387) -> (-35.5465, -14.1524)
  line L20 (-49.3351, -5.3135) -> (-38.0214, -16.6272)
  arc A1 centre (-39.8245, -12.2078) radius 4.4 clockwise from (-36.7132, -9.0966) to (-36.7132, -15.3191)
  arc A2 centre (-44.9157, -7.1167) radius 4.4 clockwise from (-48.027, -4.0054) to (-41.8044, -4.0054)
  arc A3 centre (-45.0571, -7.2581) radius 4.4 clockwise from (-48.1684, -10.3693) to (-48.1684, -4.1468)
  arc A4 centre (-39.9659, -12.3492) radius 4.4 clockwise from (-36.8547, -15.4605) to (-43.0772, -15.4605)
  point P14 (-36.784, -15.3898)
  point P15 (-48.0977, -4.0761)
  point P16 (-45.6228, -12.9149)
  point P17 (-39.2588, -6.551)
  point P27 (-43.5015, -9.7329)
  point P26 (-42.4408, -10.7936)
  midpoint L4 P14
  midpoint L2 P15
  midpoint L3 P16
  midpoint L1 P17
  perpendicular L11 L12
  parallel L11 L13
  parallel L12 L14
  coincident L10 P27
  coincident L8 P27
  perpendicular L10 L11
  coincident L9 P26
  dimension "d151" = 0.75 (= "( 1.5 / 2 ) * 1 mm")
  dimension "d152" = -0.75
  dimension "d153" = 0.75 (= "( 1.5 / 2 ) * 1 mm")
  dimension "d154" = -0.75
  dimension "d155" = -1
  dimension "d162" = 1.75 (= "0.75 mm + 1 mm")
  dimension "d163" = -1.75
extrude "Extrude27" add sketch "Sketch12" profile of L11 L12 L13 L14 L15 L16 L18 L17 along normal blind 9
fillet "Fillet11" radius 0.75
extrude "Extrude28" new body sketch "sliderclose" profile of L1 A1 L2 A2 L3 A3 L4 A4 A12 L13 A13 L14 A14 L15 A15 L16 A22 L21 A20 A21 L22 A23 L23 L24 against normal blind 1 bodies "close"
extrude "Extrude29" cut sketch "Sketch12" profile of A1 A2 L2 A3 A4 L4 L11 L12 L13 L14 L15 L16 L18 L17 L19 L20 along normal blind 8
fillet "Fillet12" radius 1
extrude "Extrude30" add of existing geometry blind 2
chamfer "Chamfer1" distance 1
sketch "Sketch13" plane through (0, 0, -30) normal (0, 0, -1) x axis (1, 0, 0)
  line L1 (45, -17.5) -> (-45, -17.5)
  line L2 (50, 12.5) -> (50, -12.5)
  line L3 (-45, 17.5) -> (45, 17.5)
  line L4 (-50, -12.5) -> (-50, 12.5)
  circle C1 centre (43.8087, -11.3516) radius 2.825
  circle C2 centre (-43.3243, 10.3844) radius 4
  arc A1 centre (-45, -12.5) radius 5 clockwise from (-45, -17.5) to (-50, -12.5)
  arc A2 centre (45, -12.5) radius 5 clockwise from (50, -12.5) to (45, -17.5)
  arc A3 centre (45, 12.5) radius 5 clockwise from (45, 17.5) to (50, 12.5)
  arc A4 centre (-45, 12.5) radius 5 clockwise from (-50, 12.5) to (-45, 17.5)
  circle C3 centre (43.8087, -11.3516) radius 4
  concentric C1 C3
  dimension "d171" diameter C3 = 8
extrude "Extrude31" cut sketch "Sketch13" profile of C1 C3 against normal blind 2
extrude "Extrude32" add of existing geometry blind 2
chamfer "Chamfer2" distance 1
sketch "Sketch14" plane through (0, 0, -30) normal (0, 0, -1) x axis (1, 0, 0)
  line L1 (45, -17.5) -> (-45, -17.5)
  line L2 (50, 12.5) -> (50, -12.5)
  line L3 (-45, 17.5) -> (45, 17.5)
  line L4 (-50, -12.5) -> (-50, 12.5)
  circle C1 centre (-43.3243, 10.3844) radius 2.825
  circle C2 centre (43.8087, -11.3516) radius 4
  arc A1 centre (-45, -12.5) radius 5 clockwise from (-45, -17.5) to (-50, -12.5)
  arc A2 centre (45, -12.5) radius 5 clockwise from (50, -12.5) to (45, -17.5)
  arc A3 centre (45, 12.5) radius 5 clockwise from (45, 17.5) to (50, 12.5)
  arc A4 centre (-45, 12.5) radius 5 clockwise from (-50, 12.5) to (-45, 17.5)
  circle C3 centre (-43.3243, 10.3844) radius 4
  concentric C1 C3
  dimension "d179" diameter C3 = 8
extrude "Extrude34" cut sketch "Sketch14" profile of C1 C3 against normal blind 2
sketch "knob" plane through (0, 0, 0) normal (0, 0, -1) x axis (1, 0, 0)
  line L1 (26.835, -2.8162) -> (26.835, 2.7156)
  line L2 (25.335, -3.536) -> (25.335, 3.4354)
  line L3 (27.035, -2.7055) -> (27.035, 2.6049)
  circle C1 centre (28.635, -0.0503) radius 14.9999
  arc A1 centre (28.635, -0.0503) radius 3.3 clockwise from (26.835, 2.7156) to (26.835, -2.8162)
  circle C2 centre (28.635, -0.0503) radius 14.6
  arc A2 centre (28.635, -0.0503) radius 4.8 clockwise from (25.335, 3.4354) to (25.335, -3.536)
  arc A3 centre (28.635, -0.0503) radius 3.1 clockwise from (27.035, 2.6049) to (27.035, -2.7055)
  dimension "d184" diameter C2 = 29.2
  dimension "d188" = 1.5
  dimension "d226" = -0.2
sketch "Sketch18" plane through (0, 0, 0) normal (0, 0, -1) x axis (1, 0, 0)
  line L1 (-49.3351, -2.4851) -> (-49.6887, -2.8387)
  line L2 (-35.193, -8.8491) -> (-41.5569, -2.4851)
  line L3 (-35.5465, -16.9808) -> (-35.193, -16.6272)
  line L4 (-49.6887, -10.6168) -> (-43.3247, -16.9808)
  line L5 (-30.5, -8.5) -> (15.0483, -8.5)
  line L6 (15.1114, 8.5) -> (-30.5, 8.5)
  line L7 (22, 14.5) -> (22, 14.509)
  line L8 (21.9803, 14.5) -> (22, 14.5)
  line L9 (52.85, 12.5) -> (52.85, -12.5)
  line L10 (-45, 20.35) -> (45, 20.35)
  line L11 (-52.85, -12.5) -> (-52.85, 12.5)
  line L12 (45, -20.35) -> (-45, -20.35)
  circle C1 centre (-43.3243, 10.3844) radius 3.225
  arc A1 centre (-45.7996, -6.7277) radius 5.5 clockwise from (-49.6887, -10.6168) to (-49.6887, -2.8387)
  arc A2 centre (-45.446, -6.3742) radius 5.5 clockwise from (-49.3351, -2.4851) to (-41.5569, -2.4851)
  arc A3 centre (-39.0821, -12.7382) radius 5.5 clockwise from (-35.193, -8.8491) to (-35.193, -16.6272)
  arc A4 centre (-39.4356, -13.0917) radius 5.5 clockwise from (-35.5465, -16.9808) to (-43.3247, -16.9808)
  arc A5 centre (28.635, -0.0503) radius 15.9999 clockwise from (15.0483, -8.5) to (15.1114, 8.5)
  arc A6 centre (-30.5, 0) radius 8.5 clockwise from (-30.5, -8.5) to (-30.5, 8.5)
  arc A7 centre (28.635, -0.0503) radius 15.9999 clockwise from (21.9803, 14.5) to (22, 14.509)
  arc A8 centre (45, 12.5) radius 7.85 clockwise from (45, 20.35) to (52.85, 12.5)
  arc A9 centre (-45, 12.5) radius 7.85 clockwise from (-52.85, 12.5) to (-45, 20.35)
  arc A10 centre (-45, -12.5) radius 7.85 clockwise from (-45, -20.35) to (-52.85, -12.5)
  arc A11 centre (45, -12.5) radius 7.85 clockwise from (52.85, -12.5) to (45, -20.35)
  circle C2 centre (43.8087, -11.3516) radius 4.5
  circle C3 centre (-43.3243, 10.3844) radius 4.5
  circle C4 centre (28.635, -0.0503) radius 14.9999
  circle C5 centre (43.8087, -11.3516) radius 3.225
  circle C6 centre (43.8087, -11.3516) radius 3.225
  concentric C2 C5
  concentric C1 C3
  dimension "d200" diameter C2 = 9
  dimension "d201" diameter C3 = 9
extrude "Extrude39" add sketch "Sketch18" profile of C1 C5 C4 C6 C2 C3 along normal blind 10.1
move "Move1" TranslateX 0 TranslateY 0 TranslateZ 1
offset_faces "OffsetFaces1" distance 1.8
offset_faces "OffsetFaces2" distance 2.5
offset_faces "OffsetFaces3" distance -2.5
extrude "Extrude48" cut of existing geometry blind -1
sketch "Sketch22" plane through (0, 0, 1) normal (0, 0, -1) x axis (1, 0, 0)
  line L1 (52.85, 12.5) -> (52.85, -12.5)
  line L2 (-45, 20.35) -> (45, 20.35)
  line L3 (-52.85, -12.5) -> (-52.85, 12.5)
  line L4 (45, -20.35) -> (-45, -20.35)
  line L5 (22, 14.5) -> (22, 14.509)
  line L6 (21.9803, 14.5) -> (22, 14.5)
  line L7 (-30.5, -8.5) -> (15.0483, -8.5)
  line L8 (15.1114, 8.5) -> (-30.5, 8.5)
  line L9 (-49.3351, -2.4851) -> (-49.6887, -2.8387)
  line L10 (-35.193, -8.8491) -> (-41.5569, -2.4851)
  line L11 (-35.5465, -16.9808) -> (-35.193, -16.6272)
  line L12 (-49.6887, -10.6168) -> (-43.3247, -16.9808)
  line L13 (-35.2637, -16.5565) -> (-35.6172, -16.9101)
  line L14 (-41.6276, -2.5558) -> (-35.2637, -8.9198)
  line L15 (-49.6179, -2.9094) -> (-49.2644, -2.5558)
  line L16 (-43.254, -16.9101) -> (-49.6179, -10.5461)
  line L17 (-39.6124, -7.9652) -> (-40.673, -6.9045)
  line L18 (-44.2086, -12.5614) -> (-39.6124, -7.9652)
  line L19 (-45.2692, -11.5007) -> (-44.2086, -12.5614)
  line L20 (-40.673, -6.9045) -> (-45.2692, -11.5007)
  line L21 (-36.4304, -9.7329) -> (-42.4408, -15.7434)
  line L22 (-42.4408, -3.7225) -> (-36.4304, -9.7329)
  line L23 (-48.4512, -9.7329) -> (-42.4408, -3.7225)
  line L24 (-42.4408, -15.7434) -> (-48.4512, -9.7329)
  line L25 (-36.2183, -9.7329) -> (-42.4408, -15.9555)
  line L26 (-42.4408, -3.5104) -> (-36.2183, -9.7329)
  line L27 (-48.6634, -9.7329) -> (-42.4408, -3.5104)
  line L28 (-42.4408, -15.9555) -> (-48.6634, -9.7329)
  arc A1 centre (45, 12.5) radius 7.85 clockwise from (45, 20.35) to (52.85, 12.5)
  arc A2 centre (-45, 12.5) radius 7.85 clockwise from (-52.85, 12.5) to (-45, 20.35)
  arc A3 centre (-45, -12.5) radius 7.85 clockwise from (-45, -20.35) to (-52.85, -12.5)
  arc A4 centre (45, -12.5) radius 7.85 clockwise from (52.85, -12.5) to (45, -20.35)
  arc A5 centre (28.635, -0.0503) radius 15.9999 clockwise from (21.9803, 14.5) to (22, 14.509)
  arc A6 centre (43.8087, -11.3516) radius 4.5 clockwise from (41.7342, -7.3583) to (39.3886, -10.5078)
  arc A7 centre (28.635, -0.0503) radius 14.9999 clockwise from (39.3886, -10.5078) to (41.7342, -7.3583)
  arc A8 centre (28.635, -0.0503) radius 15.9999 clockwise from (15.0483, -8.5) to (15.1114, 8.5)
  arc A9 centre (-30.5, 0) radius 8.5 clockwise from (-30.5, -8.5) to (-30.5, 8.5)
  arc A10 centre (-45.7996, -6.7277) radius 5.5 clockwise from (-49.6887, -10.6168) to (-49.6887, -2.8387)
  arc A11 centre (-45.446, -6.3742) radius 5.5 clockwise from (-49.3351, -2.4851) to (-41.5569, -2.4851)
  arc A12 centre (-39.0821, -12.7382) radius 5.5 clockwise from (-35.193, -8.8491) to (-35.193, -16.6272)
  arc A13 centre (-39.4356, -13.0917) radius 5.5 clockwise from (-35.5465, -16.9808) to (-43.3247, -16.9808)
  circle C1 centre (-43.3243, 10.3844) radius 4.5
  arc A14 centre (-39.4356, -13.0917) radius 5.4 clockwise from (-35.6172, -16.9101) to (-43.254, -16.9101)
  arc A15 centre (-39.0821, -12.7382) radius 5.4 clockwise from (-35.2637, -8.9198) to (-35.2637, -16.5565)
  arc A16 centre (-45.446, -6.3742) radius 5.4 clockwise from (-49.2644, -2.5558) to (-41.6276, -2.5558)
  arc A17 centre (-45.7996, -6.7277) radius 5.4 clockwise from (-49.6179, -10.5461) to (-49.6179, -2.9094)
  dimension "d245" = 0.15
extrude "Extrude49" new body sketch "Sketch22" profile of A14 L13 A15 L14 A16 L15 L16 A17 L28 L27 L26 L25 against normal blind 1
extrude "Extrude50" new body sketch "knob" profile of A1 L1 C2 A2 L2 A3 L3 against normal blind 13 bodies "KNOB"
sphere_primitive "SpherePrimitive3" Diameter 160
move_face "MoveFace3" TranslateX 0 TranslateY 0 TranslateZ 79
combine "Combine5"
chamfer "Chamfer5" distance 1.5
fillet "Fillet19" radius 11.5
fillet "Fillet20" radius 2.25
fillet "Fillet21" radius 2.2
shell "Shell6" innerThickness 2
extrude "Extrude51" sketch "knob" profile of A1 L1 A2 L2 A3 L3 blind 5
extrude "Extrude52" sketch "slider" profile of L12 L15 L16 L20 L21 L29 L17 L14 L9 L10 blind -0.8
fillet "Fillet22" radius 3.4
fillet "Fillet23" radius 4.4
sketch "Sketch26" plane through (0, 0, 6) normal (0, 0, 1) x axis (-1, 0, 0)
  line L1 (41.8044, -5.4196) -> (38.1275, -9.0966)
  line L2 (46.7542, -5.561) -> (46.6127, -5.4196)
  line L3 (43.0772, -14.0463) -> (46.7542, -10.3693)
  line L4 (38.1275, -13.9049) -> (38.2689, -14.0463)
  line L5 (-52.85, -12.5) -> (-52.85, 12.5)
  line L6 (45, -20.35) -> (-45, -20.35)
  line L7 (52.85, 12.5) -> (52.85, -12.5)
  line L8 (-45, 20.35) -> (45, 20.35)
  line L9 (-22, 14.509) -> (-22, 14.5)
  line L10 (-22, 14.5) -> (-21.9803, 14.5)
  line L11 (-16.105, -10) -> (30.5, -10)
  line L12 (30.5, 10) -> (-16.1856, 10)
  line L13 (49.1005, -7.973) -> (44.1507, -3.0233)
  line L14 (40.6152, -16.4583) -> (49.1005, -7.973)
  line L15 (44.1507, -3.0233) -> (35.6654, -11.5086)
  line L16 (35.6654, -11.5086) -> (40.6152, -16.4583)
  line L17 (50.5147, -7.973) -> (44.1507, -1.6091)
  line L18 (40.6152, -17.8725) -> (50.5147, -7.973)
  line L19 (44.1507, -1.6091) -> (34.2512, -11.5086)
  line L20 (34.2512, -11.5086) -> (40.6152, -17.8725)
  line L21 (44.1507, -3.3061) -> (35.9483, -11.5086)
  line L22 (48.8176, -7.973) -> (44.1507, -3.3061)
  line L23 (40.6152, -16.1755) -> (48.8176, -7.973)
  line L24 (35.9483, -11.5086) -> (40.6152, -16.1755)
  line L25 (44.1507, -3.094) -> (35.7361, -11.5086)
  line L26 (49.0297, -7.973) -> (44.1507, -3.094)
  line L27 (40.6152, -16.3876) -> (49.0297, -7.973)
  line L28 (35.7361, -11.5086) -> (40.6152, -16.3876)
  arc A1 centre (44.2086, -7.8238) radius 3.4 clockwise from (41.8044, -5.4196) to (46.6127, -5.4196)
  arc A2 centre (44.35, -7.9652) radius 3.4 clockwise from (46.7542, -5.561) to (46.7542, -10.3693)
  arc A3 centre (40.673, -11.6421) radius 3.4 clockwise from (43.0772, -14.0463) to (38.2689, -14.0463)
  arc A4 centre (40.5316, -11.5007) radius 3.4 clockwise from (38.1275, -13.9049) to (38.1275, -9.0966)
  arc A5 centre (-45, -12.5) radius 7.85 clockwise from (-45, -20.35) to (-52.85, -12.5)
  arc A6 centre (45, -12.5) radius 7.85 clockwise from (52.85, -12.5) to (45, -20.35)
  arc A7 centre (45, 12.5) radius 7.85 clockwise from (45, 20.35) to (52.85, 12.5)
  arc A8 centre (-45, 12.5) radius 7.85 clockwise from (-52.85, 12.5) to (-45, 20.35)
  arc A9 centre (-28.635, -0.0503) radius 15.9999 clockwise from (-22, 14.509) to (-21.9803, 14.5)
  circle C1 centre (-28.635, -0.0503) radius 14.9999
  arc A10 centre (30.5, 0) radius 10 clockwise from (30.5, 10) to (30.5, -10)
  arc A11 centre (-28.635, -0.0503) radius 15.9999 clockwise from (-16.1856, 10) to (-16.105, -10)
  dimension "d272" = 0.2
  dimension "d273" = 0.05
sketch "acrylicdisp" plane through (0, 0, 6) normal (0, 0, 1) x axis (-1, 0, 0)
  line L1 (41.8044, -5.4196) -> (38.1275, -9.0966)
  line L2 (46.7542, -5.561) -> (46.6127, -5.4196)
  line L3 (43.0772, -14.0463) -> (46.7542, -10.3693)
  line L4 (38.1275, -13.9049) -> (38.2689, -14.0463)
  line L5 (-52.85, -12.5) -> (-52.85, 12.5)
  line L6 (52.85, 12.5) -> (52.85, -12.5)
  line L7 (-22, 14.509) -> (-22, 14.5)
  line L8 (-22, 14.5) -> (-21.9803, 14.5)
  line L9 (-16.105, -10) -> (30.5, -10)
  line L10 (30.5, 10) -> (-16.1856, 10)
  line L11 (-16.105, -10) -> (30.5, -10)
  line L12 (30.5, 10) -> (-16.1856, 10)
  arc A1 centre (44.2086, -7.8238) radius 3.4 clockwise from (41.8044, -5.4196) to (46.6127, -5.4196)
  arc A2 centre (44.35, -7.9652) radius 3.4 clockwise from (46.7542, -5.561) to (46.7542, -10.3693)
  arc A3 centre (40.673, -11.6421) radius 3.4 clockwise from (43.0772, -14.0463) to (38.2689, -14.0463)
  arc A4 centre (40.5316, -11.5007) radius 3.4 clockwise from (38.1275, -13.9049) to (38.1275, -9.0966)
  arc A5 centre (45, -12.5) radius 7.85 clockwise from (52.85, -12.5) to (45, -20.35)
  arc A6 centre (45, 12.5) radius 7.85 clockwise from (45, 20.35) to (52.85, 12.5)
  arc A7 centre (-28.635, -0.0503) radius 15.9999 clockwise from (-22, 14.509) to (-21.9803, 14.5)
  arc A8 centre (30.5, 0) radius 10 clockwise from (30.5, 10) to (30.5, -10)
  arc A9 centre (-28.635, -0.0503) radius 15.9999 clockwise from (-16.1856, 10) to (-16.105, -10)
  arc A10 centre (-28.635, -0.0503) radius 15.9999 clockwise from (-16.1856, 10) to (-16.105, -10)
  arc A11 centre (30.5, 0) radius 10 clockwise from (30.5, 10) to (30.5, -10)
extrude "Extrude35" new body of existing geometry blind -2.5
combine "Combine2"
extrude "Extrude10" cut sketch "switch" profile of L31 L32 L33 L34 C2 along normal blind 46
extrude "Extrude11" cut sketch "switch" profile of L19 L20 L21 L22 L23 L24 L25 L26 L31 L32 L33 L34 L27 L28 L29 L30 along normal blind 3.5
extrude "Extrude12" sketch "switch" profile of L24 L25 L31 L32 L33 L34 C2 L27 L28 L29 L30 blind -1 bodies "buttonslider"
extrude "Extrude13" sketch "switch" profile of C2 blind 4
extrude "Extrude14" sketch "switch" profile of L24 L25 L31 L32 L33 L34 L27 L28 L29 L30 blind 1
named bodies: "Topplate", "out", "buttonslider", "switch", "close", "KNOB"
